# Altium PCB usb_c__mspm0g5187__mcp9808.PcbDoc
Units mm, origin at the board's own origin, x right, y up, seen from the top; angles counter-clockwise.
Board outline 92 x 60 mm, 2 copper layers (Top, Bottom), stack 0 mm thick; 35 components, 28 nets, 180 pads, 62 vias.
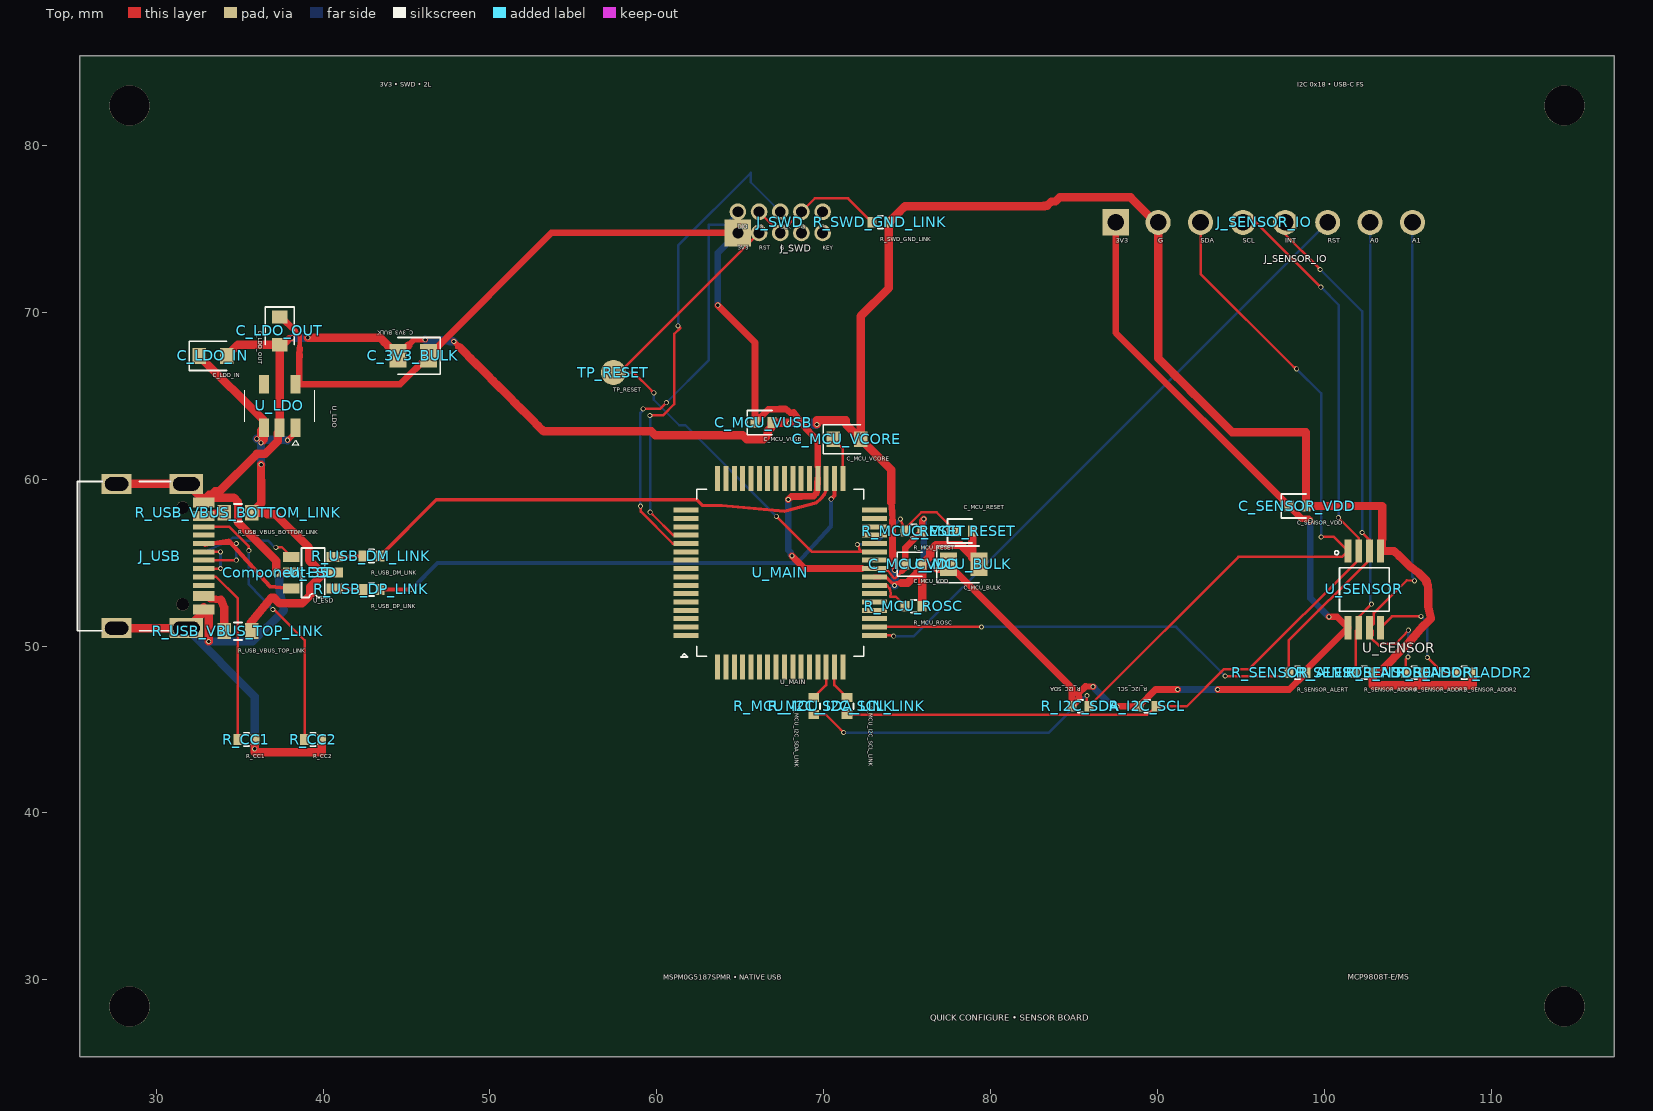
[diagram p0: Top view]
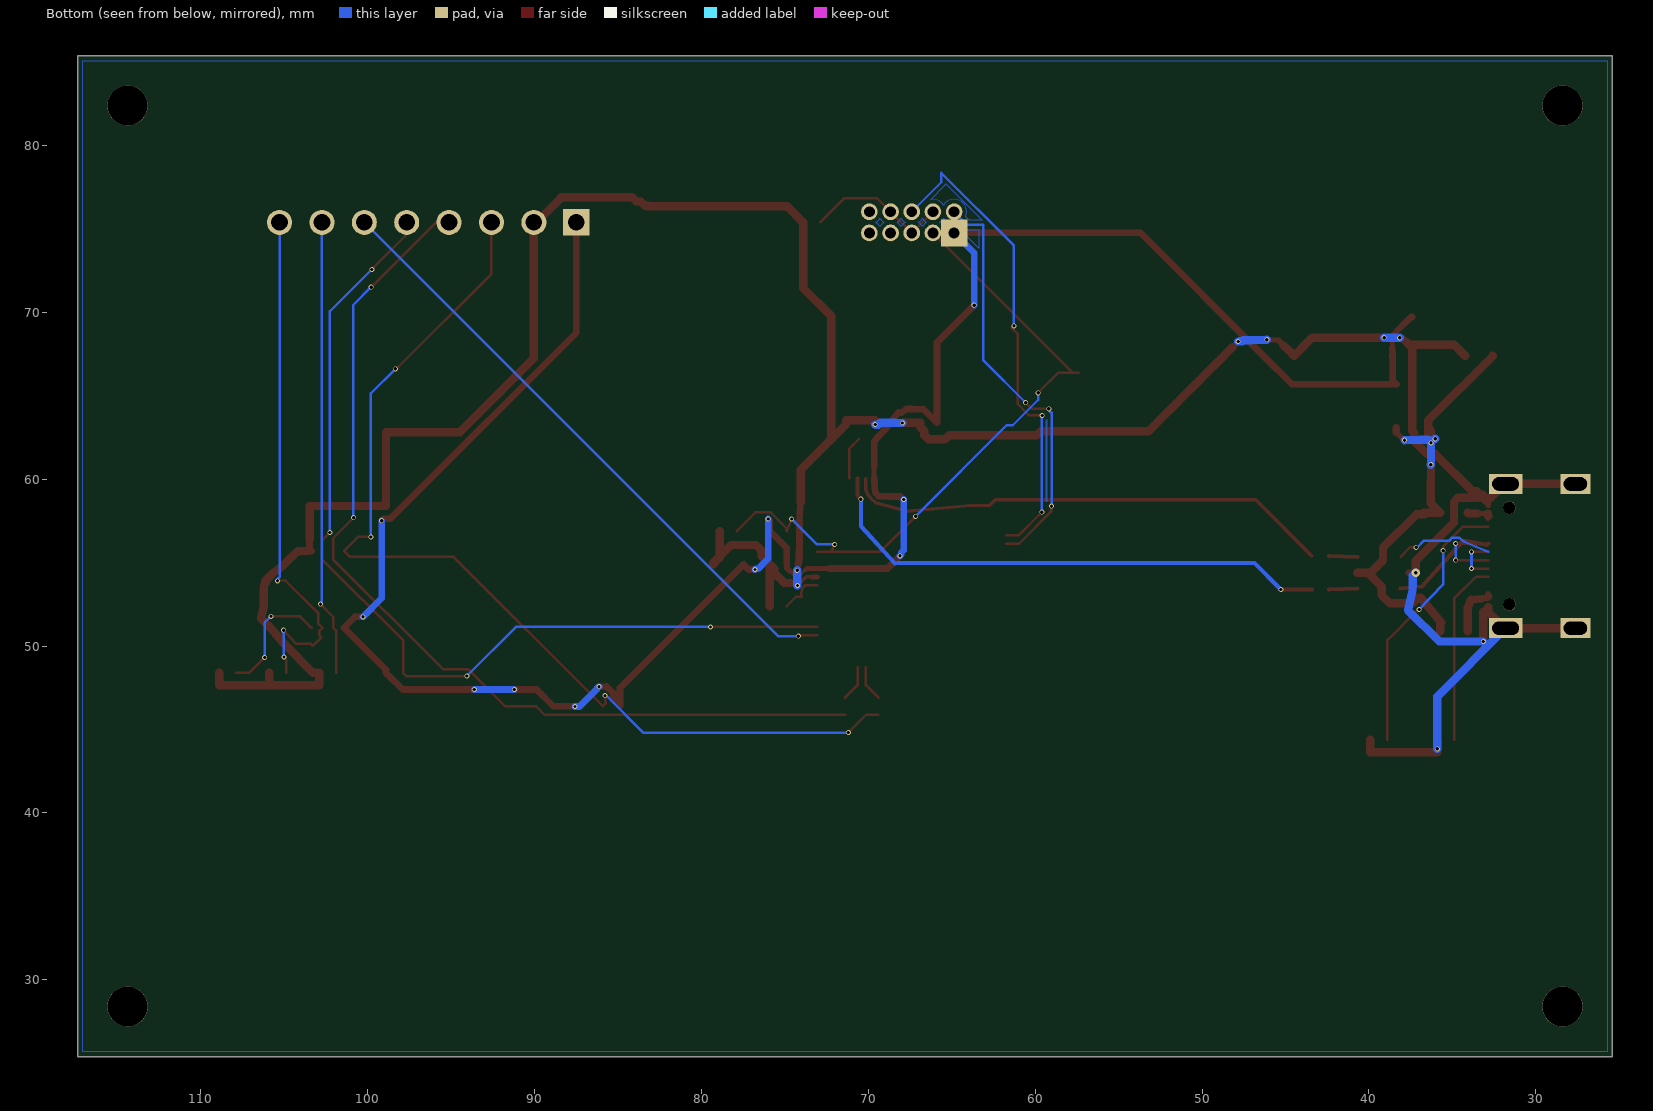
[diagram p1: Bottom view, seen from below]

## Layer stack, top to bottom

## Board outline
25.4,85.4 117.4,85.4 117.4,25.4 25.4,25.4

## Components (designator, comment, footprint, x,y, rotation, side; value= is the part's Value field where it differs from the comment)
C_3V3_BULK "" TSCIRCUIT-2.8500x1.4000mm 45.4,67.4 r180 top
C_LDO_IN "" TSCIRCUIT-2.4500x0.9500mm 33.4,67.4 r0 top
C_LDO_OUT "" TSCIRCUIT-0.9500x2.4500mm 37.4,68.9 r270 top
C_MCU_BULK "" TSCIRCUIT-2.8500x1.4000mm 78.4,54.9 r0 top
C_MCU_RESET "" TSCIRCUIT-1.5600x0.6400mm 78.4,56.9 r0 top
C_MCU_VCORE "" TSCIRCUIT-2.4500x0.9500mm 71.4,62.4 r0 top
C_MCU_VDD "" TSCIRCUIT-1.5600x0.6400mm 75.4,54.9 r0 top
C_MCU_VUSB "" TSCIRCUIT-1.5600x0.6400mm 66.4,63.4 r0 top
C_SENSOR_VDD "" TSCIRCUIT-1.5600x0.6400mm 98.4,58.4 r0 top
Component-35 "" TSCIRCUIT-0.5000x0.5000mm 37.2,54.4 r0 top
J_SENSOR_IO "" TSCIRCUIT-19.2800x1.5000mm 96.4,75.4 r0 top
J_SWD "" TSCIRCUIT-6.0800x2.2700mm 67.4,75.4 r0 top
J_USB "" TSCIRCUIT-6.7732x9.8502mm 30.113,55.4 r90 top
R_CC1 "" TSCIRCUIT-1.5600x0.6400mm 35.4,44.4 r0 top
R_CC2 "" TSCIRCUIT-1.5600x0.6400mm 39.4,44.4 r0 top
R_I2C_SCL "" TSCIRCUIT-1.5600x0.6400mm 89.4,46.4 r180 top
R_I2C_SDA "" TSCIRCUIT-1.5600x0.6400mm 85.4,46.4 r180 top
R_MCU_I2C_SCL_LINK "" TSCIRCUIT-0.6400x1.5600mm 71.4,46.4 r270 top
R_MCU_I2C_SDA_LINK "" TSCIRCUIT-0.6400x1.5600mm 69.4,46.4 r270 top
R_MCU_RESET "" TSCIRCUIT-1.5600x0.6400mm 75.4,56.9 r0 top
R_MCU_ROSC "" TSCIRCUIT-1.5600x0.6400mm 75.4,52.4 r0 top
R_SENSOR_ADDR0 "" TSCIRCUIT-1.5600x0.6400mm 102.4,48.4 r0 top
R_SENSOR_ADDR1 "" TSCIRCUIT-1.5600x0.6400mm 105.4,48.4 r0 top
R_SENSOR_ADDR2 "" TSCIRCUIT-1.5600x0.6400mm 108.4,48.4 r0 top
R_SENSOR_ALERT "" TSCIRCUIT-1.5600x0.6400mm 98.4,48.4 r0 top
R_SWD_GND_LINK "" TSCIRCUIT-1.5600x0.6400mm 73.4,75.4 r0 top
R_USB_DM_LINK "" TSCIRCUIT-1.5600x0.6400mm 42.9,55.4 r0 top
R_USB_DP_LINK "" TSCIRCUIT-1.5600x0.6400mm 42.9,53.4 r0 top
R_USB_VBUS_BOTTOM_LINK "" TSCIRCUIT-2.4500x0.9500mm 34.9,58 r0 top
R_USB_VBUS_TOP_LINK "" TSCIRCUIT-2.4500x0.9500mm 34.9,50.9 r0 top
TP_RESET "" TSCIRCUIT-1.5000x1.5000mm 57.4,66.4 r0 top
U_ESD "" TSCIRCUIT-3.6000x2.5000mm 39.4,54.4 r0 top
U_LDO "" TSCIRCUIT-2.5000x3.7000mm 37.4,64.4 r270 top
U_MAIN "" TSCIRCUIT-12.8000x12.8000mm 67.4,54.4 r0 top
U_SENSOR "" TSCIRCUIT-2.3562x5.9969mm 102.4,53.4 r0 top

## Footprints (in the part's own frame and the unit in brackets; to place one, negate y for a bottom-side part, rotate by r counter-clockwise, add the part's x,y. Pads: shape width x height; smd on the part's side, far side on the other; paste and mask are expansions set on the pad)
TSCIRCUIT-0.5000x0.5000mm [mm]
TSCIRCUIT-0.6400x1.5600mm [mm]
  rect 0.54x0.64 smd: 1(-0.51,0) 2(0.51,0)
  silkscreen extent -0.15,-0.38 0.15,0.38
TSCIRCUIT-0.9500x2.4500mm [mm]
  rect 0.8x0.95 smd: 1(-0.825,0) 2(0.825,0)
  silkscreen extent -1.43,-0.87 0.82,0.88
TSCIRCUIT-1.5000x1.5000mm [mm]
  round 1.5 smd: 1(0,0)
TSCIRCUIT-1.5600x0.6400mm [mm]
  rect 0.54x0.64 smd: 1(-0.51,0) 2(0.51,0)
  silkscreen extent -0.98,-0.72 0.51,0.72
TSCIRCUIT-2.3562x5.9969mm [mil]
  rect 15.98x55 smd: 1(-38.39,90.55) 2(-12.8,90.55) 3(12.8,90.55) 4(38.39,90.55) 5(38.39,-90.55) 6(12.8,-90.55) 7(-12.8,-90.55) 8(-38.39,-90.55)
  silkscreen extent -70,-51 59,91
TSCIRCUIT-2.4500x0.9500mm [mm]
  rect 0.8x0.95 smd: 1(-0.825,0) 2(0.825,0)
  silkscreen extent -1.42,-0.87 0.82,0.87
TSCIRCUIT-2.5000x3.7000mm [mm]
  rect 1.1x0.6 smd: 1(1.3,0.95) 2(1.3,0) 3(1.3,-0.95) 4(-1.3,-0.95) 5(-1.3,0.95)
  silkscreen extent -0.95,-2.1 2.35,2.1
TSCIRCUIT-2.8500x1.4000mm [mm]
  rect 1.025x1.4 smd: 1(-0.913,0) 2(0.913,0)
  silkscreen extent -1.63,-1.1 0.91,1.1
TSCIRCUIT-3.6000x2.5000mm [mm]
  rect 1x0.6 smd: 1(-1.3,-0.95) 2(-1.3,0) 3(-1.3,0.95) 4(1.3,0.95) 5(1.3,0) 6(1.3,-0.95)
  silkscreen extent -0.7,-1.49 0.7,1.49
TSCIRCUIT-6.0800x2.2700mm [mm]
  rect 1.6x1.6 hole 0.65: 1(-2.54,-0.635)
  round 1 hole 0.65: 2(-2.54,0.635) 3(-1.27,0.635) 4(0,0.635) 5(1.27,0.635) 6(2.54,0.635) 7(2.54,-0.635) 8(1.27,-0.635) 9(0,-0.635) 10(-1.27,-0.635)
TSCIRCUIT-6.7732x9.8502mm [mm]
  rect 0.3x1.3 smd: 1(-3.35,-2.737) 2(-3.05,-2.737) 3(-2.55,-2.737) 4(-2.25,-2.737) 5(-1.75,-2.737) 6(-1.25,-2.737) 7(-0.75,-2.737) 8(-0.25,-2.737) 9(0.25,-2.737) 10(0.75,-2.737) 11(1.25,-2.737) 12(1.75,-2.737) 13(2.55,-2.737) 14(2.25,-2.737) 15(3.35,-2.737) 16(3.05,-2.737)
  rect 1.2x2 hole 0.8 slot 1.6 at 90 deg: 17(-4.325,-1.693) 18(4.325,-1.693)
  rect 1.2x1.8 hole 0.8 slot 1.4 at 90 deg: 19(4.325,2.487) 20(-4.325,2.487)
  round 0.75 hole 0.75 unplated: NPTH-1(-2.9,-1.468) NPTH-2(2.9,-1.468)
  silkscreen extent -4.47,-0.75 4.47,4.83
TSCIRCUIT-12.8000x12.8000mm [mm]
  rect 1.5x0.3 smd: 1(-5.65,-3.75) 2(-5.65,-3.25) 3(-5.65,-2.75) 4(-5.65,-2.25) 5(-5.65,-1.75) 6(-5.65,-1.25) 7(-5.65,-0.75) 8(-5.65,-0.25) 9(-5.65,0.25) 10(-5.65,0.75) 11(-5.65,1.25) 12(-5.65,1.75) 13(-5.65,2.25) 14(-5.65,2.75) 15(-5.65,3.25) 16(-5.65,3.75) 33(5.65,3.75) 34(5.65,3.25) 35(5.65,2.75) 36(5.65,2.25) 37(5.65,1.75) 38(5.65,1.25) 39(5.65,0.75) 40(5.65,0.25) 41(5.65,-0.25) 42(5.65,-0.75) 43(5.65,-1.25) 44(5.65,-1.75) 45(5.65,-2.25) 46(5.65,-2.75) 47(5.65,-3.25) 48(5.65,-3.75)
  rect 0.3x1.5 smd: 17(-3.75,5.65) 18(-3.25,5.65) 19(-2.75,5.65) 20(-2.25,5.65) 21(-1.75,5.65) 22(-1.25,5.65) 23(-0.75,5.65) 24(-0.25,5.65) 25(0.25,5.65) 26(0.75,5.65) 27(1.25,5.65) 28(1.75,5.65) 29(2.25,5.65) 30(2.75,5.65) 31(3.25,5.65) 32(3.75,5.65) 49(3.75,-5.65) 50(3.25,-5.65) 51(2.75,-5.65) 52(2.25,-5.65) 53(1.75,-5.65) 54(1.25,-5.65) 55(0.75,-5.65) 56(0.25,-5.65) 57(-0.25,-5.65) 58(-0.75,-5.65) 59(-1.25,-5.65) 60(-1.75,-5.65) 61(-2.25,-5.65) 62(-2.75,-5.65) 63(-3.25,-5.65) 64(-3.75,-5.65)
  silkscreen extent -5.95,-5.05 5,5
TSCIRCUIT-19.2800x1.5000mm [mm]
  rect 1.6x1.6 hole 1: 1(-8.89,0)
  round 1.5 hole 1: 2(-6.35,0) 3(-3.81,0) 4(-1.27,0) 5(1.27,0) 6(3.81,0) 7(6.35,0) 8(8.89,0)

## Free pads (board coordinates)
  round 2.4 hole 2.4 unplated: NPTH-3(28.4,28.4) NPTH-4(114.4,28.4) NPTH-5(28.4,82.4) NPTH-6(114.4,82.4)

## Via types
v1: diameter 0.3, hole 0.2, Top to Bottom, 61 vias
v2: diameter 0.5, hole 0.2, Top to Bottom, 1 vias

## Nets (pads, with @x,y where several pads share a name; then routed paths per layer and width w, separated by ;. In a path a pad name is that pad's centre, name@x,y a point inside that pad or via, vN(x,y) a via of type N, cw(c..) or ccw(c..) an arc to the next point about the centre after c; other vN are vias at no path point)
".J_SWD > .pin2 to .U_MAIN > .pin12": J_SWD.2 U_MAIN.12 | length 25.1
  Top w0.15: v1(59.02,58.395) 59.042,58.373 59.042,58.063 60.955,56.15 U_MAIN.12 ; v1(59.186,64.225) 60.203,64.225 60.542,64.564 v1(60.567,64.589)
  Bottom w0.15: v1(59.02,58.395) 59.02,63.98 59.136,64.096 59.136,64.175 v1(59.186,64.225) ; v1(60.567,64.589) 63.111,67.133 63.111,75.246 64.071,75.246 J_SWD.2
".J_SWD > .pin4 to .U_MAIN > .pin13": J_SWD.4 U_MAIN.13 | length 29.2
  Top w0.15: v1(59.586,63.828) 60.363,63.828 61.048,64.513 61.048,68.71 61.414,69.076 61.394,69.076 v1(61.273,69.197) ; v1(59.603,58.031) 59.757,57.877 59.757,57.874 60.981,56.65 U_MAIN.13
  Bottom w0.15: v1(59.586,63.828) 59.554,63.796 59.554,63.759 59.603,63.71 v1(59.603,58.031) ; v1(61.273,69.197) 61.273,74.009 65.631,78.367 65.631,77.804 J_SWD.4
".U_MAIN > .pin42 to .R_MCU_ROSC > .pin1": R_MCU_ROSC.1 U_MAIN.42 | length 2.6
  Top w0.15: U_MAIN.42 73.8,53.65 73.957,53.464 74.024,53.172 73.987,52.959 74,52.962 74.328,52.962 R_MCU_ROSC.1
GND: C_3V3_BULK.2 C_LDO_IN.2 C_LDO_OUT.2 C_MCU_BULK.2 C_MCU_RESET.2 C_MCU_VCORE.2 C_MCU_VDD.2 C_MCU_VUSB.2 C_SENSOR_VDD.2 J_SENSOR_IO.2 J_USB.1 J_USB.2 J_USB.15 J_USB.16 J_USB.17 J_USB.18 J_USB.19 J_USB.20 R_CC1.2 R_CC2.2 R_MCU_ROSC.2 R_SENSOR_ADDR0.2 R_SENSOR_ADDR1.2 R_SENSOR_ADDR2.2 R_SWD_GND_LINK.2 U_ESD.2 U_LDO.2 U_MAIN.41 U_SENSOR.4 | length 205.2
  Top w0.188: U_MAIN.41@73.384,54.15 73.718,54.149 73.985,53.892 v1(74.251,53.635) ; U_MAIN.41@73.702,54.151 73.901,53.976 74.1,53.8 74.119,53.781
  Top w0.2: U_MAIN.41@73.376,54.151 U_MAIN.41@73.702,54.151 ; 74.119,53.781 74.356,53.781
  Top w0.225: 74.356,53.781 74.649,53.784
  Top w0.275: J_USB.16 J_USB.15@33.04,58.641
  Top w0.3: J_USB.1@32.699,51.9 J_USB.1 J_USB.1@32.849,52.2 ; J_USB.15@32.699,58.9 J_USB.15 ; J_USB.2 J_USB.1@32.999,52.2 ; J_USB.16@32.849,58.6 J_USB.15 ; J_USB.15@32.999,58.9 J_USB.15 ; J_USB.15@33.04,58.641 33.231,58.832 33.332,58.832 33.4,58.9 33.499,58.9
  Top w0.301: U_MAIN.41 U_MAIN.41@73.384,54.15
  Top w0.302: U_MAIN.41 U_MAIN.41@73.376,54.151
  Top w0.312: 45.418,68.331 45.675,68.35 45.931,68.369 v1(46.119,68.365) ; 74.202,54.914 v1(74.267,54.546)
  Top w0.325: J_USB.16 J_USB.16@32.849,58.6 ; J_USB.1@32.999,52.2 J_USB.1@33.141,52.058 ; v1(47.832,68.263) 48.169,67.926
  Top w0.35: 37.968,68.441 38.124,68.441 v1(38.153,68.477) ; 45.108,68.02 45.418,68.331
  Top w0.375: 74.057,58.607 74.088,58.316 74.119,58.025 74.122,57.568
  Top w0.4: 37.2,54.4 U_ESD.2@37.6,54.4
  Top w0.406: 103.488,56.398 103.488,55.813 U_SENSOR.4 U_SENSOR.4@103.578,55.702
  Top w0.425: C_LDO_OUT.2@37.785,68.258 37.968,68.441 ; 74.122,57.568 74.125,57.111
  Top w0.437: 74.125,57.111 74.13,56.197 74.136,55.282 74.202,54.914
  Top w0.5: J_USB.20 J_USB.17 31.874,51.075 32.474,51.675 32.699,51.9 ; J_USB.19 J_USB.18 31.874,59.725 32.474,59.125 32.699,58.9 ; J_USB.1@32.849,52.2 J_USB.2 ; 32.999,58.9 33.164,59.065 33.204,59.025 33.275,59.025 33.525,59.275 33.775,59.275 36.025,61.525 36.525,61.525 37.275,62.275 37.275,62.775 37.4,62.9 U_LDO.2 C_LDO_OUT.2 ; v1(33.141,50.275) 33.141,50.721 33.141,51.167 33.141,51.612 J_USB.1@33.141,52.058 ; 33.499,58.9 34.65,58.9 34.9,58.65 34.9,57.4 37.2,55.1 37.2,54.4 ; C_LDO_IN.2 34.9,68.075 C_LDO_OUT.2 ; v1(35.9,43.85) 35.9,43.904 35.91,43.914 R_CC1.2 35.91,43.65 39.91,43.65 R_CC2.2 ; C_LDO_OUT.2@37.785,68.258 37.603,68.075 C_LDO_OUT.2 ; v1(39.081,68.491) 39.56,68.491 40.04,68.491 40.519,68.491 40.999,68.491 41.478,68.491 41.958,68.491 42.437,68.491 42.917,68.491 43.396,68.491 43.669,68.218 43.942,67.946 44.215,67.673 C_3V3_BULK.2 44.798,67.71 45.108,68.02 ; 48.169,67.926 48.506,67.589 48.843,67.252 49.18,66.915 49.517,66.578 49.854,66.241 50.191,65.904 50.528,65.567 50.865,65.23 51.202,64.893 51.539,64.556 51.876,64.219 52.213,63.882 52.55,63.545 52.887,63.208 53.225,62.87 53.712,62.87 54.199,62.87 54.686,62.87 55.174,62.87 55.661,62.87 56.148,62.87 56.635,62.87 57.123,62.87 57.61,62.87 58.097,62.87 58.584,62.87 59.072,62.87 59.559,62.87 59.68,62.87 59.9,62.65 65.15,62.65 65.4,62.4 66.4,62.4 66.65,62.65 66.65,62.9 66.9,63.15 66.9,63.4 C_MCU_VUSB.2 67.41,63.4 67.91,63.4 v1(67.959,63.379) ; v1(69.589,63.289) 69.589,63.539 71.336,63.539 71.336,63.289 71.632,62.993 71.929,62.696 C_MCU_VCORE.2 ; 74.057,58.607 74.054,59.1 74.052,59.592 74.05,60.085 74.047,60.578 73.744,60.881 73.44,61.185 73.136,61.489 72.832,61.793 72.529,62.096 C_MCU_VCORE.2 ; 74.649,53.784 74.797,53.787 75.037,53.787 75.65,54.4 75.65,54.64 C_MCU_VDD.2 ; R_MCU_ROSC.2 C_MCU_VDD.2 ; C_MCU_RESET.2 78.91,55.303 C_MCU_BULK.2 79.313,54.988 78.233,56.067 76.733,56.067 76.4,55.733 76.4,55.4 75.9,54.9 C_MCU_VDD.2 ; 103.488,56.398 103.488,58.4 C_SENSOR_VDD.2 98.91,62.83 94.48,62.83 94.139,63.171 93.798,63.512 93.458,63.852 93.117,64.193 92.776,64.534 92.435,64.875 92.095,65.215 91.754,65.556 91.413,65.897 91.072,66.238 90.732,66.578 90.391,66.919 90.05,67.26 90.05,67.739 90.05,68.218 90.05,68.696 90.05,69.175 90.05,69.654 90.05,70.133 90.05,70.612 90.05,71.091 90.05,71.569 90.05,72.048 90.05,72.527 90.05,73.006 90.05,73.485 90.05,73.964 90.05,74.442 90.05,74.921 J_SENSOR_IO.2 89.9,75.4 88.4,76.9 84.15,76.9 83.9,76.65 83.65,76.65 83.4,76.4 83.202,76.4 83.235,76.366 82.748,76.366 82.261,76.366 81.773,76.366 81.286,76.366 80.799,76.366 80.311,76.366 79.824,76.366 79.337,76.366 78.849,76.366 78.362,76.366 77.875,76.366 77.387,76.366 76.9,76.366 76.413,76.366 75.925,76.366 75.438,76.366 74.951,76.366 74.876,76.366 74.554,76.044 74.232,75.722 R_SWD_GND_LINK.2 73.91,71.464 72.225,69.779 72.225,69.287 72.225,68.795 72.225,68.303 72.225,67.812 72.225,67.32 72.225,66.828 72.225,66.336 72.225,65.844 72.225,65.352 72.225,64.86 72.225,64.368 72.225,63.876 72.225,63.384 72.225,62.892 C_MCU_VCORE.2 ; U_SENSOR.4@103.578,55.702 103.782,55.704 104.19,55.707 104.51,55.393 104.831,55.079 105.152,54.765 105.65,54.4 106.15,53.9 106.113,53.823 106.227,53.657 106.229,53.246 106.231,52.836 106.232,52.426 106.4,51.65 105.9,51.15 105.927,51.233 105.025,50.15 103.275,48.4 R_SENSOR_ADDR0.2 102.91,47.65 105.91,47.65 ; R_SENSOR_ADDR2.2 108.91,47.65 105.91,47.65 ; 105.91,47.65 R_SENSOR_ADDR1.2 105.91,47.65
  Bottom w0.5: J_USB.17 35.9,46.981 v1(35.9,43.85) ; v1(33.141,50.275) 35.775,50.275 37.65,52.15 37.39,53.334 37.381,53.784 37.371,54.235 37.2,54.4 ; v1(38.153,68.477) 39.067,68.477 v1(39.081,68.491) ; v1(46.119,68.365) 46.593,68.354 47.067,68.344 47.541,68.333 47.595,68.278 47.771,68.278 v1(47.832,68.263) ; v1(67.959,63.379) 68.401,63.386 68.844,63.393 69.286,63.4 69.422,63.263 69.563,63.263 v1(69.589,63.289) ; v1(74.251,53.635) 74.267,53.651 v1(74.267,54.546)
MAIN_RESET: C_MCU_RESET.1 J_SWD.10 R_MCU_RESET.1 TP_RESET.1 U_MAIN.38 | length 41.9
  Top w0.15: v1(59.82,65.179) 59.711,65.288 59.711,65.306 58.616,66.4 TP_RESET.1 57.765,66.4 J_SWD.10 ; v1(67.163,57.782) 69.295,55.65 U_MAIN.38 72.3,55.65 72.123,55.827 72.11,55.994 v1(72.024,56.094) ; v1(74.6,57.62) R_MCU_RESET.1 74.89,57.059 75.855,58.025 76.765,58.025 C_MCU_RESET.1
  Bottom w0.15: v1(59.82,65.179) 59.82,64.767 61.347,63.24 61.712,63.24 67.11,57.842 67.11,57.835 v1(67.163,57.782) ; v1(72.024,56.094) 73.071,56.094 74.451,57.474 74.454,57.474 v1(74.6,57.62)
MCU_I2C_SCL_LOCAL: R_MCU_I2C_SCL_LINK.1 U_MAIN.50 | length 2.2
  Top w0.15: U_MAIN.50 70.65,47.66 R_MCU_I2C_SCL_LINK.1
MCU_I2C_SDA_LOCAL: R_MCU_I2C_SDA_LINK.1 U_MAIN.51 | length 2.2
  Top w0.15: R_MCU_I2C_SDA_LINK.1 70.15,47.66 U_MAIN.51
MSPM0_VCORE: C_MCU_VCORE.1 U_MAIN.32 | length 2.6
  Top w0.15: C_MCU_VCORE.1 71.15,61.825 U_MAIN.32
SENSOR_ADDR0: J_SENSOR_IO.7 R_SENSOR_ADDR0.1 U_SENSOR.7 | length 27.5
  Top w0.15: R_SENSOR_ADDR0.1 101.89,50.915 U_SENSOR.7 102.075,51.759 v1(102.837,52.521)
  Bottom w0.15: J_SENSOR_IO.7 102.75,52.63 102.859,52.521 v1(102.837,52.521)
SENSOR_ADDR1: J_SENSOR_IO.8 R_SENSOR_ADDR1.1 U_SENSOR.6 | length 32.1
  Top w0.15: R_SENSOR_ADDR1.1 104.89,49.215 105.011,49.336 v1(105.028,49.353) ; v1(105.045,50.957) 104.312,50.14 103.418,50.14 103.312,50.012 102.8,50.495 102.91,50.669 102.91,50.678 102.91,50.915 U_SENSOR.6 102.979,51.365 102.983,51.988 104.948,53.946 v1(105.412,53.912)
  Bottom w0.15: v1(105.028,49.353) 105.028,50.746 105.103,50.821 105.103,50.899 v1(105.045,50.957) ; J_SENSOR_IO.8 105.29,54.146 105.463,53.972 105.463,53.963 v1(105.412,53.912)
SENSOR_ADDR2: R_SENSOR_ADDR2.1 U_SENSOR.5 | length 7.4
  Top w0.15: U_SENSOR.5 104.064,51.789 v1(105.808,51.789) ; v1(106.186,49.324) 106.24,49.27 106.25,49.27 107.121,48.4 R_SENSOR_ADDR2.1
  Bottom w0.15: v1(105.808,51.789) 105.895,51.713 105.895,51.703 106.186,51.412 v1(106.186,49.324)
SENSOR_INT: J_SENSOR_IO.5 R_SENSOR_ALERT.1 U_MAIN.47 U_SENSOR.3 | length 57.2
  Top w0.15: U_MAIN.47 79.3,51.15 v1(79.46,51.15) ; v1(94.069,48.207) 97.697,48.207 R_SENSOR_ALERT.1 97.891,50.364 102.736,55.189 U_SENSOR.3 102.725,56.364 v1(102.273,56.816) ; J_SENSOR_IO.5 97.67,74.683 99.638,72.715 99.638,72.706 v1(99.765,72.579)
  Bottom w0.15: v1(79.46,51.15) 91.126,51.15 94.01,48.266 v1(94.069,48.207) ; v1(99.765,72.579) 102.271,70.073 102.271,57.008 102.271,56.818 v1(102.273,56.816)
SENSOR_RESET: J_SENSOR_IO.6 U_MAIN.48 | length 37.5
  Top w0.15: U_MAIN.48 74.017,50.65 74.04,50.627 74.173,50.627 v1(74.2,50.6)
  Bottom w0.15: v1(74.2,50.6) 75.41,50.6 J_SENSOR_IO.6
SENSOR_SCL: J_SENSOR_IO.4 R_I2C_SCL.1 R_MCU_I2C_SCL_LINK.2 U_SENSOR.2 | length 58.1
  Top w0.15: R_MCU_I2C_SCL_LINK.2 89.4,45.89 R_I2C_SCL.1 91.772,46.4 93.991,48.619 95.494,48.618 102.086,55.19 U_SENSOR.2 102.075,56.474 v1(100.851,57.698) ; J_SENSOR_IO.4 95.906,75.392 99.776,71.533 v1(99.798,71.516)
  Bottom w0.15: v1(99.798,71.516) 100.882,70.432 100.882,57.729 v1(100.851,57.698)
SENSOR_SDA: J_SENSOR_IO.3 R_I2C_SDA.1 R_MCU_I2C_SDA_LINK.2 U_SENSOR.1 | length 61.7
  Top w0.15: R_MCU_I2C_SDA_LINK.2 70.13,45.89 71.028,44.992 v1(71.2,44.82) ; v1(85.788,47.031) 85.748,46.562 R_I2C_SDA.1 94.856,55.346 101.071,55.346 U_SENSOR.1 100.58,56.545 v1(99.82,56.545) ; J_SENSOR_IO.3 92.59,72.313 98.185,66.718 98.256,66.718 v1(98.35,66.624)
  Bottom w0.15: v1(71.2,44.82) 83.496,44.82 85.742,47.066 v1(85.788,47.031) ; v1(98.35,66.624) 99.814,65.16 99.814,56.732 99.814,56.551 v1(99.82,56.545)
swd-ground-1-to-2: J_SWD.3 J_SWD.5 J_SWD.9 R_SWD_GND_LINK.1 | length 8.8
  Top w0.15: J_SWD.3 J_SWD.9 J_SWD.5 69.481,76.846 71.471,76.846 71.471,76.819 R_SWD_GND_LINK.1
usb-dm-device: R_USB_DM_LINK.1 U_ESD.4 | length 1.7
  Top w0.25: U_ESD.4 R_USB_DM_LINK.1
usb-dm-mcu: R_USB_DM_LINK.2 U_MAIN.30 | length 29.5
  Top w0.2: R_USB_DM_LINK.2 46.788,58.778 62.407,58.778 62.757,58.427 63.9,58.426 67.652,58.093 69.565,58.597 69.824,58.831 70.05,59.098 70.15,59.34 U_MAIN.30
usb-dm-port-tie: J_USB.7 J_USB.9 U_ESD.3 | length 8.9
  Top w0.15: J_USB.7 v1(33.85,54.65) ; J_USB.9 v1(33.85,55.65) ; v1(37.166,55.926) 37.524,55.926 U_ESD.3
  Bottom w0.15: 32.849,55.65 33.553,55.947 34.321,56.274 34.582,56.507 35.02,56.503 35.182,56.331 35.272,56.308 36.716,56.308 37.095,55.929 37.163,55.929 v1(37.166,55.926) ; v1(33.85,54.65) v1(33.85,55.65)
usb-dp-device: R_USB_DP_LINK.1 U_ESD.6 | length 1.7
  Top w0.25: U_ESD.6 R_USB_DP_LINK.1
usb-dp-mcu: R_USB_DP_LINK.2 U_MAIN.31 | length 31.6
  Top w0.25: R_USB_DP_LINK.2 v1(45.28,53.4) ; v1(70.451,58.812) 70.49,58.851 70.49,58.867 70.65,59.027 U_MAIN.31
  Bottom w0.25: v1(45.28,53.4) 45.353,53.473 46.866,54.986 68.225,54.984 68.4,54.95 70.451,57.214 v1(70.451,58.812)
usb-dp-port-tie: J_USB.8 J_USB.10 U_ESD.1 | length 11.5
  Top w0.15: J_USB.8 v1(34.8,55.15) ; J_USB.10 v1(34.8,56.15)
  Top w0.25: J_USB.10 32.924,56.075 34.343,56.34 36.821,53.573 U_ESD.1
  Bottom w0.15: v1(34.8,55.15) v1(34.8,56.15)
USB_CC1: J_USB.6 R_CC1.1 | length 11
  Top w0.15: J_USB.6 32.871,54.172 33.563,54.172 34.89,52.846 R_CC1.1
USB_CC2: J_USB.12 R_CC2.1 | length 16.2
  Top w0.15: J_USB.12 34.363,57.162 35.552,55.962 v1(35.545,55.728) ; v1(36.986,52.2) 37.091,52.155 38.89,50.356 R_CC2.1
  Bottom w0.15: v1(35.545,55.728) 35.548,55.725 35.548,55.485 35.548,53.698 v1(36.986,52.2)
USB_VBUS_BOTTOM_LOCAL: J_USB.13 J_USB.14 R_USB_VBUS_BOTTOM_LINK.1 | length 1.5
  Top w0.3: J_USB.14 J_USB.14@32.849,57.8 ; J_USB.13 32.927,57.95 33.005,57.95 33.083,57.95 33.161,57.95 33.239,57.95 33.317,57.95 33.394,57.95 33.472,57.95 33.499,57.95
  Top w0.475: J_USB.13@32.849,57.8 J_USB.13 ; 33.499,57.95 R_USB_VBUS_BOTTOM_LINK.1@33.762,57.95
  Top w0.5: R_USB_VBUS_BOTTOM_LINK.1@33.762,57.95 34.025,57.95 R_USB_VBUS_BOTTOM_LINK.1
USB_VBUS_TOP_LOCAL: J_USB.3 J_USB.4 R_USB_VBUS_TOP_LINK.1 | length 3.3
  Top w0.3: J_USB.4 32.849,53 J_USB.3 J_USB.3@32.878,52.877
  Top w0.35: J_USB.3@32.878,52.877 J_USB.3@33.222,52.85
  Top w0.45: J_USB.3@33.222,52.85 33.565,52.824 33.884,52.775
  Top w0.5: 33.884,52.775 34.075,52.314 34.075,51.843 34.075,51.371 R_USB_VBUS_TOP_LINK.1
VBUS5: C_LDO_IN.1 R_USB_VBUS_BOTTOM_LINK.2 R_USB_VBUS_TOP_LINK.2 U_ESD.5 U_LDO.1 U_LDO.3 | length 29.7
  Top w0.312: v1(36.025,62.425) U_LDO.3@36.275,62.556 ; v1(36.275,62.186) 36.407,62.318
  Top w0.325: v1(37.864,62.342) 38.022,62.486 U_LDO.1@38.35,62.814
  Top w0.45: 36.407,62.318 36.407,62.368 ; U_LDO.1@38.35,62.814 U_LDO.1
  Top w0.475: 36.288,59.95 36.288,60.413 v1(36.288,60.875)
  Top w0.5: C_LDO_IN.1 36.45,63.525 U_LDO.3 ; R_USB_VBUS_TOP_LINK.2 35.725,51.387 35.65,51.4 36.9,52.9 37.067,52.9 37.4,52.567 38.733,52.567 39.233,53.067 39.233,53.567 40.067,54.4 40.567,54.4 U_ESD.5 39.9,54.4 39.15,55.15 39.15,55.9 37.15,57.9 36.65,57.9 36.65,57.925 36.725,58 36.225,58 R_USB_VBUS_BOTTOM_LINK.2 36.006,58.281 36.288,58.563 36.288,59.025 36.288,59.488 36.288,59.95 ; U_LDO.3@36.275,62.556 36.275,62.925 U_LDO.3 ; 36.407,62.368 36.45,62.411 36.45,62.756 U_LDO.3
  Bottom w0.5: v1(36.025,62.425) 36.379,62.291 36.462,62.373 36.929,62.363 37.397,62.352 v1(37.864,62.342) ; v1(36.275,62.186) 36.275,60.888 v1(36.288,60.875)
VCC_3V3: C_3V3_BULK.1 C_LDO_OUT.1 C_MCU_BULK.1 C_MCU_VDD.1 C_MCU_VUSB.1 C_SENSOR_VDD.1 J_SENSOR_IO.1 J_SWD.1 R_I2C_SCL.2 R_I2C_SDA.2 R_MCU_RESET.2 R_SENSOR_ALERT.2 U_LDO.5 U_MAIN.29 U_MAIN.40 U_SENSOR.8 | length 138.4
  Top w0.15: U_MAIN.40@73.766,54.567 73.84,54.547 74.03,54.304 74.22,54.061 74.275,54.065
  Top w0.162: 74.275,54.065 74.48,54.27
  Top w0.175: 74.48,54.27 74.685,54.475
  Top w0.275: 38.309,68.903 38.594,68.628 38.59,68.241 38.587,67.854 ; U_MAIN.40@73.683,54.65 U_MAIN.40@73.766,54.567
  Top w0.288: U_MAIN.40@73.367,54.65 U_MAIN.40@73.683,54.65
  Top w0.3: 72.3,54.65 72.669,54.65 U_MAIN.40 U_MAIN.40@73.367,54.65
  Top w0.304: U_MAIN.29 69.651,60.418 U_MAIN.29@69.652,60.785
  Top w0.325: 74.685,54.475 74.89,54.68 C_MCU_VDD.1
  Top w0.35: 38.025,69.178 38.309,68.903
  Top w0.363: 69.387,58.987 69.562,59.163 69.6,59.25
  Top w0.387: 38.583,67.467 38.587,67.854 ; 69.6,59.25 U_MAIN.29@69.617,59.517
  Top w0.393: U_MAIN.29@69.617,59.517 69.633,59.783 U_MAIN.29
  Top w0.4: C_LDO_OUT.1 37.456,69.728 37.74,69.453 38.025,69.178 ; 38.583,67.467 38.58,67.08 38.576,66.693 38.572,66.306 38.569,65.919 U_LDO.5 44.613,65.7 C_3V3_BULK.1 53.672,74.771 J_SWD.1 ; v1(63.655,70.439) 63.674,70.42 65.89,68.204 C_MCU_VUSB.1 66.157,63.667 66.423,63.933 66.69,64.2 67.032,64.205 67.374,64.21 67.715,64.215 68.019,63.997 68.2,64 68.767,63.271 68.989,63.017 69.211,62.764 69.433,62.51 69.656,62.256 69.655,61.888 69.654,61.521 69.653,61.153 U_MAIN.29@69.652,60.785 ; v1(67.879,58.789) 68.035,58.94 68.066,58.971 68.366,58.971 68.666,58.971 69.021,58.986 69.387,58.987 ; v1(68.1,55.411) 68.354,55.157 68.607,54.904 68.861,54.65 69.242,54.65 69.623,54.65 70.003,54.65 70.384,54.65 70.765,54.65 71.146,54.65 71.527,54.65 71.908,54.65 72.288,54.65 72.3,54.65 ; C_MCU_VDD.1 74.89,55.88 R_MCU_RESET.2 75.91,57.522 76,57.612 v1(76.001,57.619) ; v1(76.791,54.592) 77.18,54.592 C_MCU_BULK.1 84.89,47.498 R_I2C_SDA.2 85.316,46.826 85.293,47.199 85.699,47.592 v1(86.149,47.575) ; J_SENSOR_IO.1 87.51,68.78 C_SENSOR_VDD.1 98.662,57.628 99.065,57.628 v1(99.171,57.522) ; v1(87.58,46.382) 87.585,46.388 87.645,46.388 87.657,46.4 R_I2C_SCL.2 89.889,47.399 90.976,47.399 v1(91.22,47.399) ; v1(93.62,47.398) 97.908,47.398 R_SENSOR_ALERT.2 98.91,48.585 U_SENSOR.8 100.766,51.759 v1(100.287,51.759)
  Bottom w0.4: v1(63.655,70.439) 63.655,73.56 J_SWD.1 ; v1(67.879,58.789) 67.879,58.41 67.879,58.031 67.879,57.652 67.879,57.273 67.879,56.894 67.879,56.515 67.879,56.136 67.879,55.757 68.035,55.6 68.035,55.476 v1(68.1,55.411) ; v1(76.001,57.619) 76,55.247 76.615,54.632 76.75,54.632 v1(76.791,54.592) ; v1(86.149,47.575) 86.264,47.46 86.264,47.429 87.31,46.382 v1(87.58,46.382) ; v1(91.22,47.399) 93.467,47.399 93.468,47.398 v1(93.62,47.398) ; v1(99.171,57.522) 99.171,52.872 100.226,51.817 100.229,51.817 v1(100.287,51.759)
pads on no net: J_SWD.6 J_SWD.7 J_SWD.8 J_USB.5 J_USB.11 J_USB.NPTH-1 J_USB.NPTH-2 U_LDO.4 U_MAIN.1 U_MAIN.2 U_MAIN.3 U_MAIN.4 U_MAIN.5 U_MAIN.6 U_MAIN.7 U_MAIN.8 U_MAIN.9 U_MAIN.10 U_MAIN.11 U_MAIN.14 U_MAIN.15 U_MAIN.16 U_MAIN.17 U_MAIN.18 U_MAIN.19 U_MAIN.20 U_MAIN.21 U_MAIN.22 U_MAIN.23 U_MAIN.24 U_MAIN.25 U_MAIN.26 U_MAIN.27 U_MAIN.28 U_MAIN.33 U_MAIN.34 U_MAIN.35 U_MAIN.36 U_MAIN.37 U_MAIN.39 U_MAIN.43 U_MAIN.44 U_MAIN.45 U_MAIN.46 U_MAIN.49 U_MAIN.52 U_MAIN.53 U_MAIN.54 U_MAIN.55 U_MAIN.56 U_MAIN.57 U_MAIN.58 U_MAIN.59 U_MAIN.60 U_MAIN.61 U_MAIN.62 U_MAIN.63 U_MAIN.64
copper on no net:
  other v2: 37.2,54.4

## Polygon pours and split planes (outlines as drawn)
GND on Bottom (solid): 117.1,85.1 25.7,85.1 25.7,25.7 117.1,25.7
GND on Bottom (solid): 59.295,63.555 59.295,58.684 59.303,58.678 59.328,58.647 59.328,63.525 59.303,63.545
GND on Bottom (solid): 65.371,77.718 63.174,75.521 63.958,75.521 64.173,75.737 64.167,75.748 64.124,75.889 64.11,76.035 64.124,76.181 64.167,76.322 64.236,76.452 64.33,76.565 64.443,76.659 64.573,76.728 64.714,76.771 64.86,76.785 65.006,76.771 65.147,76.728 65.277,76.659 65.39,76.565 65.484,76.452 65.495,76.43 65.506,76.452 65.6,76.565 65.713,76.659 65.843,76.728 65.984,76.771 66.13,76.785 66.275,76.771 65.437,77.609 65.403,77.651 65.377,77.698
GND on Bottom (solid): 65.495,75.64 65.484,75.618 65.399,75.515 65.591,75.515 65.506,75.618
GND on Bottom (solid): 65.61,75.496 65.61,75.304 65.713,75.389 65.735,75.4 65.713,75.411
GND on Bottom (solid): 69.305,75.64 69.294,75.618 69.2,75.505 69.087,75.411 69.065,75.4 69.087,75.389 69.2,75.295 69.294,75.182 69.305,75.16 69.316,75.182 69.41,75.295 69.523,75.389 69.545,75.4 69.523,75.411 69.41,75.505 69.316,75.618
GND on Bottom (solid): 68.035,75.64 68.024,75.618 67.93,75.505 67.817,75.411 67.795,75.4 67.817,75.389 67.93,75.295 68.024,75.182 68.035,75.16 68.046,75.182 68.14,75.295 68.253,75.389 68.275,75.4 68.253,75.411 68.14,75.505 68.046,75.618
GND on Bottom (solid): 66.765,75.64 66.754,75.618 66.66,75.505 66.547,75.411 66.525,75.4 66.547,75.389 66.66,75.295 66.754,75.182 66.765,75.16 66.776,75.182 66.87,75.295 66.983,75.389 67.005,75.4 66.983,75.411 66.87,75.505 66.776,75.618
GND on Bottom (solid): 64.11,74.975 64.071,74.971 63.386,74.971 63.386,73.856 64.11,74.581

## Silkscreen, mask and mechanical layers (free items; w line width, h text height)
Top Overlay:
  text "3V3 • SWD • 2L" at 43.4,83.4 h0.48
  text "I2C 0x18 • USB-C FS" at 98.4,83.4 h0.5
  text "MSPM0G5187SPMR • NATIVE USB" at 60.4,29.9 h0.52
  text "MCP9808T-E/MS" at 101.4,29.9 h0.55
  text "QUICK CONFIGURE • SENSOR BOARD" at 76.4,27.4 h0.65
